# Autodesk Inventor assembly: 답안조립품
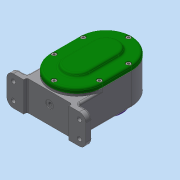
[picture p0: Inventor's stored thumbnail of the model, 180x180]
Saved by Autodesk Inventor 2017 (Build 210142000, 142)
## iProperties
Part Number: 답안조립품
Material: 일반
Document SubType Name: Assembly
Designer: MRC
Author: MRC
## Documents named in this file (19)
- C:\Users\MRC\Desktop\710609V1016\답안조립품.iam
- C:\Users\MRC\Desktop\710609V1016\스퍼기어 A.ipt
- C:\Users\MRC\Desktop\710609V1016\스퍼기어 B.ipt
- C:\Users\MRC\Desktop\710609V1016\오일 실 12 22 7.ipt
- C:\Users\MRC\Desktop\710609V1016\축 A.ipt
- C:\Users\MRC\Desktop\710609V1016\축 B.ipt
- C:\Users\MRC\Desktop\710609V1016\칼라.ipt
- C:\Users\MRC\Desktop\710609V1016\커버 A.ipt
- C:\Users\MRC\Desktop\710609V1016\커버 B.ipt
- C:\Users\MRC\Desktop\710609V1016\키 4 x 4 x 12.ipt
- C:\Users\MRC\Desktop\710609V1016\키 5 x 5 x 12.ipt
- C:\Users\MRC\Desktop\710609V1016\개스킷 A.ipt
- C:\Users\MRC\Desktop\710609V1016\개스킷 B.ipt
- C:\Users\MRC\Desktop\710609V1016\베어링 6001.ipt
- 베어링 6001.ipt
- C:\Users\MRC\Desktop\710609V1016\베어링 6002.ipt
- 베어링 6002.ipt
- C:\Users\MRC\Desktop\710609V1016\볼트 M4.ipt
- C:\Users\MRC\Desktop\710609V1016\본체.ipt
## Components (2 placed, 2 different names)
1. 개스킷 A:1
2. 개스킷 B:1
